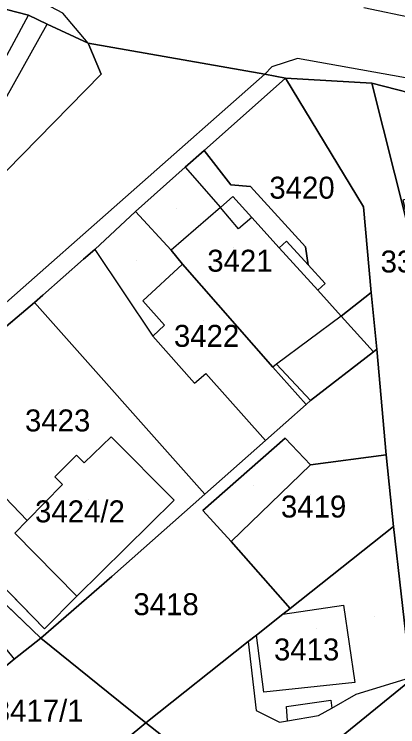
# Model space of a CAD drawing. Extents: x -262657 to -261595, y -1238015 to -1237156.
# Drawn here: x -262065.5 to -262030.6, y -1237601.5 to -1237536.7 of the extents above; entities that cross this region are included whole.
import ezdxf

# ---------------------------------------------------------------- set-up
doc = ezdxf.new("R2010")
doc.units = 0
for name, color, linetype in [('body_kn', 7, 'Continuous'), ('kladpar_druhypozemkov', 7, 'Continuous'), ('kladpar_hranice', 7, 'Continuous'), ('kladpar_parcelnecisla', 7, 'Continuous'), ('kladpar_plochy', 7, 'Continuous'), ('zappar_hrandruhpozemk', 7, 'Continuous')]:
    doc.layers.add(name, color=color, linetype=linetype)

msp = doc.modelspace()

# ---------------------------------------------------------------- linework, layer by layer
at = {"layer": 'body_kn'}
for p, q in [((-262064.22, -1237536.75), (-262064.22, -1237536.75)), ((-262062.54, -1237537.56), (-262062.54, -1237537.56)), ((-262058.8, -1237539.3), (-262058.8, -1237539.3)), ((-262058.8, -1237539.3), (-262058.8, -1237539.3)), ((-262039.74, -1237540.69), (-262039.74, -1237540.69)), ((-262042.06, -1237541.45), (-262042.06, -1237541.45)), ((-262057.6, -1237542.11), (-262057.6, -1237542.11)), ((-262042.71, -1237542.13), (-262042.71, -1237542.13)), ((-262042.71, -1237542.13), (-262042.71, -1237542.13)), ((-262040.84, -1237542.49), (-262040.84, -1237542.49)), ((-262040.84, -1237542.49), (-262040.84, -1237542.49)), ((-262032.96, -1237542.94), (-262032.96, -1237542.94)), ((-262048.24, -1237549.06), (-262048.24, -1237549.06)), ((-262049.96, -1237550.59), (-262049.96, -1237550.59)), ((-262049.96, -1237550.59), (-262049.96, -1237550.59)), ((-262045.81, -1237552.2), (-262045.81, -1237552.2)), ((-262044.02, -1237552.34), (-262044.02, -1237552.34)), ((-262045.62, -1237553.26), (-262045.62, -1237553.26)), ((-262046.75, -1237554.24), (-262046.75, -1237554.24)), ((-262046.75, -1237554.24), (-262046.75, -1237554.24)), ((-262033.72, -1237554.19), (-262033.72, -1237554.19)), ((-262054.48, -1237554.61), (-262054.48, -1237554.61)), ((-262043.9, -1237555.16), (-262043.9, -1237555.16)), ((-262043.9, -1237555.16), (-262043.9, -1237555.16)), ((-262045.1, -1237556.2), (-262045.1, -1237556.2)), ((-262040.73, -1237557.31), (-262040.73, -1237557.31)), ((-262039.01, -1237557.84), (-262039.01, -1237557.84)), ((-262058.2, -1237558.07), (-262058.2, -1237558.07)), ((-262058.2, -1237558.07), (-262058.2, -1237558.07)), ((-262051.25, -1237558.15), (-262051.25, -1237558.15)), ((-262041.4, -1237557.92), (-262041.4, -1237557.92)), ((-262041.4, -1237557.92), (-262041.4, -1237557.92)), ((-262059.22, -1237558.95), (-262059.22, -1237558.95)), ((-262050.21, -1237559.41), (-262050.21, -1237559.41)), ((-262038.76, -1237559.48), (-262038.76, -1237559.48)), ((-262038.76, -1237559.48), (-262038.76, -1237559.48)), ((-262037.22, -1237561.18), (-262037.22, -1237561.18)), ((-262062.93, -1237562.25), (-262062.93, -1237562.25)), ((-262062.93, -1237562.25), (-262062.93, -1237562.25)), ((-262037.89, -1237561.79), (-262037.89, -1237561.79)), ((-262033.04, -1237561.99), (-262033.04, -1237561.99)), ((-262063.69, -1237562.9), (-262063.69, -1237562.9)), ((-262053.81, -1237562.75), (-262053.81, -1237562.75)), ((-262035.77, -1237564.14), (-262035.77, -1237564.14)), ((-262035.77, -1237564.14), (-262035.77, -1237564.14)), ((-262051.85, -1237564.96), (-262051.85, -1237564.96)), ((-262052.92, -1237565.98), (-262052.92, -1237565.98)), ((-262032.81, -1237567.4), (-262032.81, -1237567.4)), ((-262032.5, -1237567.16), (-262032.5, -1237567.16)), ((-262032.5, -1237567.16), (-262032.5, -1237567.16)), ((-262041.98, -1237568.78), (-262041.98, -1237568.78)), ((-262041.64, -1237568.53), (-262041.64, -1237568.53)), ((-262048.08, -1237569.38), (-262048.08, -1237569.38)), ((-262049.13, -1237570.26), (-262049.13, -1237570.26)), ((-262038.54, -1237571.83), (-262038.54, -1237571.83)), ((-262038.54, -1237571.83), (-262038.54, -1237571.83)), ((-262038.95, -1237572.19), (-262038.95, -1237572.19)), ((-262056.69, -1237575.13), (-262056.69, -1237575.13)), ((-262040.87, -1237575.24), (-262040.87, -1237575.24)), ((-262042.65, -1237575.46), (-262042.65, -1237575.46)), ((-262059.85, -1237576.8), (-262059.85, -1237576.8)), ((-262031.65, -1237576.78), (-262031.65, -1237576.78)), ((-262031.65, -1237576.78), (-262031.65, -1237576.78)), ((-262059.15, -1237577.49), (-262059.15, -1237577.49)), ((-262038.55, -1237577.69), (-262038.55, -1237577.69)), ((-262061.82, -1237578.77), (-262061.82, -1237578.77)), ((-262061.13, -1237579.47), (-262061.13, -1237579.47)), ((-262048.18, -1237580.34), (-262048.18, -1237580.34)), ((-262050.98, -1237580.9), (-262050.98, -1237580.9)), ((-262048.36, -1237581.83), (-262048.36, -1237581.83)), ((-262064.35, -1237582.74), (-262064.35, -1237582.74)), ((-262064.35, -1237582.74), (-262064.35, -1237582.74)), ((-262030.98, -1237583.29), (-262030.98, -1237583.29)), ((-262030.98, -1237583.29), (-262030.98, -1237583.29)), ((-262065.49, -1237583.9), (-262065.49, -1237583.9)), ((-262045.79, -1237584.67), (-262045.79, -1237584.67)), ((-262045.79, -1237584.67), (-262045.79, -1237584.67)), ((-262056.65, -1237587.84), (-262056.65, -1237587.84)), ((-262059.83, -1237589.65), (-262059.83, -1237589.65)), ((-262040.41, -1237590.77), (-262040.41, -1237590.77)), ((-262035.55, -1237590.46), (-262035.55, -1237590.46)), ((-262041.07, -1237591.29), (-262041.07, -1237591.29)), ((-262041.07, -1237591.29), (-262041.07, -1237591.29)), ((-262062.79, -1237592.62), (-262062.79, -1237592.62)), ((-262063.12, -1237593.45), (-262063.12, -1237593.45)), ((-262063.12, -1237593.45), (-262063.12, -1237593.45)), ((-262043.47, -1237593.19), (-262043.47, -1237593.19)), ((-262044.22, -1237593.78), (-262044.22, -1237593.78)), ((-262044.22, -1237593.78), (-262044.22, -1237593.78)), ((-262065.53, -1237595.37), (-262065.53, -1237595.37)), ((-262034.52, -1237597.49), (-262034.52, -1237597.49)), ((-262056.98, -1237598.42), (-262056.98, -1237598.42)), ((-262042.8, -1237598.37), (-262042.8, -1237598.37)), ((-262034.39, -1237598.56), (-262034.39, -1237598.56)), ((-262036.69, -1237599.11), (-262036.69, -1237599.11)), ((-262040.75, -1237599.67), (-262040.75, -1237599.67)), ((-262036.62, -1237599.83), (-262036.62, -1237599.83)), ((-262043.5, -1237600.04), (-262043.5, -1237600.04)), ((-262037.81, -1237600.51), (-262037.81, -1237600.51)), ((-262053.55, -1237601.16), (-262053.55, -1237601.16)), ((-262041.38, -1237601.1), (-262041.38, -1237601.1)), ((-262040.64, -1237600.98), (-262040.64, -1237600.98))]:
    msp.add_line(p, q, dxfattribs=at)
at = {"layer": 'kladpar_druhypozemkov'}
for p, q in [((-262039.24, -1237552), (-262039.24, -1237552)), ((-262050.74, -1237554.36), (-262050.74, -1237554.36)), ((-262045.58, -1237557.94), (-262045.58, -1237557.94)), ((-262054.39, -1237559.06), (-262054.39, -1237559.06)), ((-262048.32, -1237564.51), (-262048.32, -1237564.51)), ((-262061.39, -1237572.67), (-262061.39, -1237572.67)), ((-262043.75, -1237579.56), (-262043.75, -1237579.56)), ((-262038.54, -1237580.38), (-262038.54, -1237580.38)), ((-262058.81, -1237580.82), (-262058.81, -1237580.82)), ((-262051.6, -1237589.33), (-262051.6, -1237589.33)), ((-262032.74, -1237591.47), (-262032.74, -1237591.47)), ((-262038.03, -1237592.62), (-262038.03, -1237592.62)), ((-262063.49, -1237599.25), (-262063.49, -1237599.25))]:
    msp.add_line(p, q, dxfattribs=at)
at = {"layer": 'kladpar_hranice'}
for points in [[(-262021.6, -1237545.84), (-262032.96, -1237542.94), (-262040.84, -1237542.49), (-262042.71, -1237542.13), (-262058.8, -1237539.3), (-262062.54, -1237537.56), (-262064.22, -1237536.75), (-262078.85, -1237532.95), (-262088.85, -1237530.38), (-262092.23, -1237529.48), (-262094.29, -1237528.94), (-262098.86, -1237527.8), (-262109.74, -1237525.5), (-262112.64, -1237524.8), (-262114.11, -1237524.36), (-262120.57, -1237522.58), (-262131.12, -1237519.93)], [(-262078.85, -1237532.95), (-262064.22, -1237536.75), (-262062.54, -1237537.56), (-262058.8, -1237539.3), (-262057.6, -1237542.11), (-262070.57, -1237555.33), (-262072.25, -1237554.91), (-262073.85, -1237554.47), (-262083.14, -1237552.21), (-262078.85, -1237532.95)], [(-262113.92, -1237604.85), (-262120, -1237601.39), (-262121.24, -1237601.28), (-262122.86, -1237600.4), (-262122.24, -1237599.28), (-262120.21, -1237600.52), (-262113.99, -1237594.34), (-262109.31, -1237589.66), (-262106.11, -1237586.39), (-262098.57, -1237579.94), (-262091.36, -1237573.71), (-262089.88, -1237572.05), (-262085.88, -1237567.52), (-262083.16, -1237564.51), (-262081.16, -1237562.71), (-262079.08, -1237560.37), (-262073.85, -1237554.47), (-262072.25, -1237554.91), (-262070.57, -1237555.33), (-262057.6, -1237542.11), (-262058.8, -1237539.3)], [(-262058.8, -1237539.3), (-262042.71, -1237542.13), (-262040.84, -1237542.49), (-262048.24, -1237549.06), (-262049.96, -1237550.59), (-262054.48, -1237554.61), (-262058.2, -1237558.07), (-262059.22, -1237558.95), (-262062.93, -1237562.25), (-262063.69, -1237562.9), (-262071.96, -1237569.89), (-262074.11, -1237571.73), (-262075.14, -1237572.58), (-262079.15, -1237575.94), (-262110.93, -1237604.68)], [(-262038.76, -1237559.48), (-262039.01, -1237557.84), (-262044.02, -1237552.34), (-262045.81, -1237552.2), (-262048.24, -1237549.06), (-262040.84, -1237542.49), (-262033.72, -1237554.19), (-262033.04, -1237561.99), (-262035.77, -1237564.14), (-262037.89, -1237561.79), (-262037.22, -1237561.18), (-262038.76, -1237559.48)], [(-262040.84, -1237542.49), (-262032.96, -1237542.94), (-262029.86, -1237555.24), (-262029.25, -1237560.87), (-262027.58, -1237574.94), (-262024.94, -1237587.76), (-262025.63, -1237587.92), (-262020.7, -1237605.65), (-261996.42, -1237600.03), (-261974.52, -1237594.83), (-261971.52, -1237603.32), (-261994.15, -1237607.67), (-262017.2, -1237612.1), (-262026.45, -1237613.9), (-262027.87, -1237614.17), (-262029.54, -1237597.37), (-262029.55, -1237597.08), (-262029.61, -1237595.57), (-262030.98, -1237583.29), (-262031.65, -1237576.78), (-262032.5, -1237567.16), (-262033.04, -1237561.99), (-262033.72, -1237554.19), (-262040.84, -1237542.49)], [(-262029.86, -1237555.24), (-262032.96, -1237542.94), (-262021.6, -1237545.84)], [(-262038.54, -1237571.83), (-262038.95, -1237572.19), (-262041.98, -1237568.78), (-262050.21, -1237559.41), (-262051.25, -1237558.15), (-262054.48, -1237554.61), (-262049.96, -1237550.59), (-262048.24, -1237549.06), (-262045.81, -1237552.2), (-262044.02, -1237552.34), (-262039.01, -1237557.84), (-262038.76, -1237559.48), (-262037.22, -1237561.18), (-262037.89, -1237561.79), (-262035.77, -1237564.14), (-262033.04, -1237561.99), (-262032.5, -1237567.16), (-262032.81, -1237567.4), (-262038.54, -1237571.83)], [(-262062.93, -1237562.25), (-262059.22, -1237558.95), (-262058.2, -1237558.07), (-262054.48, -1237554.61), (-262051.25, -1237558.15), (-262050.21, -1237559.41), (-262041.98, -1237568.78), (-262038.95, -1237572.19), (-262042.65, -1237575.46), (-262048.18, -1237580.34), (-262063.69, -1237562.9), (-262062.93, -1237562.25)], [(-262071.96, -1237569.89), (-262063.69, -1237562.9), (-262048.18, -1237580.34)], [(-262032.5, -1237567.16), (-262031.65, -1237576.78), (-262038.55, -1237577.69), (-262040.87, -1237575.24), (-262048.36, -1237581.83), (-262045.79, -1237584.67), (-262040.41, -1237590.77), (-262041.07, -1237591.29), (-262043.47, -1237593.19), (-262044.22, -1237593.78), (-262053.55, -1237601.16), (-262056.98, -1237598.42), (-262063.12, -1237593.45), (-262056.65, -1237587.84), (-262048.18, -1237580.34), (-262042.65, -1237575.46), (-262038.95, -1237572.19), (-262038.54, -1237571.83), (-262032.81, -1237567.4), (-262032.5, -1237567.16)], [(-262048.18, -1237580.34), (-262056.65, -1237587.84), (-262063.12, -1237593.45), (-262069.99, -1237586.88), (-262075.78, -1237579.99), (-262079.15, -1237575.94), (-262075.14, -1237572.58), (-262074.11, -1237571.73), (-262071.96, -1237569.89)], [(-262050.98, -1237580.9), (-262056.69, -1237575.13), (-262059.15, -1237577.49), (-262059.85, -1237576.8), (-262061.82, -1237578.77), (-262061.13, -1237579.47), (-262064.35, -1237582.74), (-262067.05, -1237579.95), (-262070.79, -1237576.11), (-262074.92, -1237580.13), (-262062.79, -1237592.62), (-262059.83, -1237589.65), (-262050.98, -1237580.9)], [(-262064.35, -1237582.74), (-262061.13, -1237579.47), (-262061.82, -1237578.77), (-262059.85, -1237576.8), (-262059.15, -1237577.49), (-262056.69, -1237575.13), (-262050.98, -1237580.9), (-262059.83, -1237589.65), (-262065.49, -1237583.9), (-262064.35, -1237582.74)], [(-262031.65, -1237576.78), (-262030.98, -1237583.29), (-262040.41, -1237590.77), (-262045.79, -1237584.67), (-262048.36, -1237581.83), (-262040.87, -1237575.24), (-262038.55, -1237577.69), (-262031.65, -1237576.78)], [(-262074.92, -1237580.13), (-262070.79, -1237576.11), (-262067.05, -1237579.95), (-262064.35, -1237582.74), (-262065.49, -1237583.9), (-262059.83, -1237589.65), (-262062.79, -1237592.62), (-262074.92, -1237580.13)], [(-262030.98, -1237583.29), (-262029.61, -1237595.57), (-262029.55, -1237597.08), (-262029.54, -1237597.37), (-262043.72, -1237608.92), (-262053.55, -1237601.16), (-262044.22, -1237593.78), (-262043.47, -1237593.19), (-262041.07, -1237591.29), (-262040.41, -1237590.77), (-262030.98, -1237583.29)], [(-262092.51, -1237617.76), (-262095.86, -1237615.41), (-262097.1, -1237614.58), (-262071.65, -1237593.69), (-262072.12, -1237593.14), (-262074.19, -1237590.6), (-262073.9, -1237590.31), (-262069.99, -1237586.88), (-262063.12, -1237593.45), (-262065.53, -1237595.37), (-262071.64, -1237600.45), (-262078.5, -1237606.01), (-262092.51, -1237617.76)], [(-262063.12, -1237593.45), (-262056.98, -1237598.42), (-262053.55, -1237601.16), (-262060.54, -1237606.97), (-262065.19, -1237611.06), (-262068.03, -1237613.46), (-262070.14, -1237610.88), (-262068.57, -1237609.5), (-262073.25, -1237604), (-262077.31, -1237607.46), (-262078.5, -1237606.01), (-262071.64, -1237600.45), (-262065.53, -1237595.37), (-262063.12, -1237593.45)], [(-262043.72, -1237608.92), (-262029.54, -1237597.37), (-262027.87, -1237614.17), (-262029.06, -1237615.25), (-262030.78, -1237613.12), (-262033.66, -1237615.13), (-262043.72, -1237608.92)], [(-262071.24, -1237632.02), (-262076.13, -1237628.59), (-262081.64, -1237624.86), (-262077.61, -1237621.48), (-262068.03, -1237613.46), (-262065.19, -1237611.06), (-262060.54, -1237606.97), (-262053.55, -1237601.16), (-262043.72, -1237608.92), (-262045.53, -1237610.37), (-262054.2, -1237617.65), (-262071.24, -1237632.02)]]:
    msp.add_lwpolyline(points, dxfattribs=at)
at = {"layer": 'kladpar_plochy'}
for p, q in [((-262071.96, -1237569.89), (-262063.69, -1237562.9)), ((-262063.69, -1237562.9), (-262048.18, -1237580.34)), ((-262056.69, -1237575.13), (-262059.15, -1237577.49)), ((-262050.98, -1237580.9), (-262056.69, -1237575.13)), ((-262059.85, -1237576.8), (-262061.82, -1237578.77)), ((-262059.15, -1237577.49), (-262059.85, -1237576.8)), ((-262061.82, -1237578.77), (-262061.13, -1237579.47)), ((-262061.13, -1237579.47), (-262064.35, -1237582.74)), ((-262074.92, -1237580.13), (-262062.79, -1237592.62)), ((-262064.35, -1237582.74), (-262067.05, -1237579.95)), ((-262048.18, -1237580.34), (-262056.65, -1237587.84)), ((-262059.83, -1237589.65), (-262050.98, -1237580.9)), ((-262063.12, -1237593.45), (-262069.99, -1237586.88)), ((-262056.65, -1237587.84), (-262063.12, -1237593.45)), ((-262062.79, -1237592.62), (-262059.83, -1237589.65))]:
    msp.add_line(p, q, dxfattribs=at)
for points in [[(-262021.6, -1237545.84), (-262032.96, -1237542.94), (-262040.84, -1237542.49), (-262042.71, -1237542.13), (-262058.8, -1237539.3), (-262062.54, -1237537.56), (-262064.22, -1237536.75), (-262078.85, -1237532.95), (-262088.85, -1237530.38), (-262092.23, -1237529.48), (-262094.29, -1237528.94), (-262098.86, -1237527.8), (-262109.74, -1237525.5), (-262112.64, -1237524.8), (-262114.11, -1237524.36), (-262120.57, -1237522.58), (-262131.12, -1237519.93)], [(-262070.57, -1237555.33), (-262057.6, -1237542.11), (-262058.8, -1237539.3), (-262042.71, -1237542.13), (-262040.84, -1237542.49), (-262048.24, -1237549.06), (-262049.96, -1237550.59), (-262054.48, -1237554.61), (-262058.2, -1237558.07), (-262059.22, -1237558.95), (-262062.93, -1237562.25), (-262063.69, -1237562.9), (-262071.96, -1237569.89)]]:
    msp.add_lwpolyline(points, dxfattribs=at)
for points in [[(-262078.85, -1237532.95), (-262064.22, -1237536.75), (-262062.54, -1237537.56), (-262058.8, -1237539.3), (-262057.6, -1237542.11), (-262070.57, -1237555.33), (-262072.25, -1237554.91), (-262073.85, -1237554.47), (-262083.14, -1237552.21)], [(-262038.76, -1237559.48), (-262039.01, -1237557.84), (-262044.02, -1237552.34), (-262045.81, -1237552.2), (-262048.24, -1237549.06), (-262040.84, -1237542.49), (-262033.72, -1237554.19), (-262033.04, -1237561.99), (-262035.77, -1237564.14), (-262037.89, -1237561.79), (-262037.22, -1237561.18)], [(-262040.84, -1237542.49), (-262032.96, -1237542.94), (-262029.86, -1237555.24), (-262029.25, -1237560.87), (-262027.58, -1237574.94), (-262024.94, -1237587.76), (-262025.63, -1237587.92), (-262020.7, -1237605.65), (-261996.42, -1237600.03), (-261974.52, -1237594.83), (-261971.52, -1237603.32), (-261994.15, -1237607.67), (-262017.2, -1237612.1), (-262026.45, -1237613.9), (-262027.87, -1237614.17), (-262029.54, -1237597.37), (-262029.55, -1237597.08), (-262029.61, -1237595.57), (-262030.98, -1237583.29), (-262031.65, -1237576.78), (-262032.5, -1237567.16), (-262033.04, -1237561.99), (-262033.72, -1237554.19)], [(-262009.62, -1237556.09), (-262009.52, -1237556.43), (-262013.23, -1237557.53), (-262021.57, -1237561.48), (-262028.2, -1237564.31), (-262028.83, -1237560.77), (-262027.22, -1237560.39), (-262026.97, -1237561.32), (-262016.83, -1237558.58), (-262017, -1237557.97), (-262010.43, -1237556.41), (-262010.95, -1237553.56), (-262018.33, -1237552.98), (-262019.4, -1237548.91), (-262029.55, -1237551.65), (-262029.11, -1237553.29), (-262030.15, -1237553.58), (-262029.72, -1237555.23), (-262029.86, -1237555.24), (-262032.96, -1237542.94), (-262021.6, -1237545.84), (-262002.32, -1237549.14), (-262005.42, -1237555.01), (-262005.41, -1237555.13)], [(-262038.54, -1237571.83), (-262038.95, -1237572.19), (-262041.98, -1237568.78), (-262050.21, -1237559.41), (-262051.25, -1237558.15), (-262054.48, -1237554.61), (-262049.96, -1237550.59), (-262048.24, -1237549.06), (-262045.81, -1237552.2), (-262044.02, -1237552.34), (-262039.01, -1237557.84), (-262038.76, -1237559.48), (-262037.22, -1237561.18), (-262037.89, -1237561.79), (-262035.77, -1237564.14), (-262033.04, -1237561.99), (-262032.5, -1237567.16), (-262032.81, -1237567.4)], [(-262062.93, -1237562.25), (-262059.22, -1237558.95), (-262058.2, -1237558.07), (-262054.48, -1237554.61), (-262051.25, -1237558.15), (-262050.21, -1237559.41), (-262041.98, -1237568.78), (-262038.95, -1237572.19), (-262042.65, -1237575.46), (-262048.18, -1237580.34), (-262063.69, -1237562.9)], [(-262032.5, -1237567.16), (-262031.65, -1237576.78), (-262038.55, -1237577.69), (-262040.87, -1237575.24), (-262048.36, -1237581.83), (-262045.79, -1237584.67), (-262040.41, -1237590.77), (-262041.07, -1237591.29), (-262043.47, -1237593.19), (-262044.22, -1237593.78), (-262053.55, -1237601.16), (-262056.98, -1237598.42), (-262063.12, -1237593.45), (-262056.65, -1237587.84), (-262048.18, -1237580.34), (-262042.65, -1237575.46), (-262038.95, -1237572.19), (-262038.54, -1237571.83), (-262032.81, -1237567.4)], [(-262064.35, -1237582.74), (-262061.13, -1237579.47), (-262061.82, -1237578.77), (-262059.85, -1237576.8), (-262059.15, -1237577.49), (-262056.69, -1237575.13), (-262050.98, -1237580.9), (-262059.83, -1237589.65), (-262065.49, -1237583.9)], [(-262031.65, -1237576.78), (-262030.98, -1237583.29), (-262040.41, -1237590.77), (-262045.79, -1237584.67), (-262048.36, -1237581.83), (-262040.87, -1237575.24), (-262038.55, -1237577.69)], [(-262074.92, -1237580.13), (-262070.79, -1237576.11), (-262067.05, -1237579.95), (-262064.35, -1237582.74), (-262065.49, -1237583.9), (-262059.83, -1237589.65), (-262062.79, -1237592.62)], [(-262030.98, -1237583.29), (-262029.61, -1237595.57), (-262029.55, -1237597.08), (-262029.54, -1237597.37), (-262043.72, -1237608.92), (-262053.55, -1237601.16), (-262044.22, -1237593.78), (-262043.47, -1237593.19), (-262041.07, -1237591.29), (-262040.41, -1237590.77)], [(-262092.51, -1237617.76), (-262095.86, -1237615.41), (-262097.1, -1237614.58), (-262071.65, -1237593.69), (-262072.12, -1237593.14), (-262074.19, -1237590.6), (-262073.9, -1237590.31), (-262069.99, -1237586.88), (-262063.12, -1237593.45), (-262065.53, -1237595.37), (-262071.64, -1237600.45), (-262078.5, -1237606.01)], [(-262063.12, -1237593.45), (-262056.98, -1237598.42), (-262053.55, -1237601.16), (-262060.54, -1237606.97), (-262065.19, -1237611.06), (-262068.03, -1237613.46), (-262070.14, -1237610.88), (-262068.57, -1237609.5), (-262073.25, -1237604), (-262077.31, -1237607.46), (-262078.5, -1237606.01), (-262071.64, -1237600.45), (-262065.53, -1237595.37)], [(-262043.72, -1237608.92), (-262029.54, -1237597.37), (-262027.87, -1237614.17), (-262029.06, -1237615.25), (-262030.78, -1237613.12), (-262033.66, -1237615.13)], [(-262071.24, -1237632.02), (-262076.13, -1237628.59), (-262081.64, -1237624.86), (-262077.61, -1237621.48), (-262068.03, -1237613.46), (-262065.19, -1237611.06), (-262060.54, -1237606.97), (-262053.55, -1237601.16), (-262043.72, -1237608.92), (-262045.53, -1237610.37), (-262054.2, -1237617.65)]]:
    msp.add_lwpolyline(points, close=True, dxfattribs=at)
at = {"layer": 'zappar_hrandruhpozemk'}
for p, q in [((-262033.7, -1237536.05), (-262003.5, -1237542.37)), ((-262073.85, -1237554.47), (-262064.22, -1237536.75)), ((-262072.25, -1237554.91), (-262062.54, -1237537.56)), ((-261992.8, -1237549.03), (-262039.74, -1237540.69)), ((-262042.71, -1237542.13), (-262113.92, -1237604.85)), ((-262046.75, -1237554.24), (-262051.25, -1237558.15)), ((-262045.1, -1237556.2), (-262046.75, -1237554.24)), ((-262043.9, -1237555.16), (-262041.4, -1237557.92)), ((-262058.2, -1237558.07), (-262052.92, -1237565.98)), ((-262041.4, -1237557.92), (-262037.89, -1237561.79)), ((-262035.77, -1237564.14), (-262041.64, -1237568.53)), ((-262035.77, -1237564.14), (-262032.81, -1237567.4)), ((-262052.92, -1237565.98), (-262049.13, -1237570.26)), ((-262041.64, -1237568.53), (-262041.98, -1237568.78)), ((-262041.64, -1237568.53), (-262038.54, -1237571.83)), ((-262045.79, -1237584.67), (-262038.55, -1237577.69)), ((-262069.19, -1237590.89), (-262065.53, -1237595.37)), ((-262041.07, -1237591.29), (-262035.55, -1237590.46)), ((-262035.55, -1237590.46), (-262034.52, -1237597.49)), ((-262040.75, -1237599.67), (-262036.69, -1237599.11)), ((-262036.69, -1237599.11), (-262036.62, -1237599.83)), ((-262040.64, -1237600.98), (-262040.75, -1237599.67)), ((-262040.64, -1237600.98), (-262037.81, -1237600.51))]:
    msp.add_line(p, q, dxfattribs=at)
for points in [[(-262058.8, -1237539.3), (-262061.1, -1237536.57), (-262064.52, -1237534.73)], [(-262039.74, -1237540.69), (-262042.06, -1237541.45), (-262042.71, -1237542.13)], [(-262049.96, -1237550.59), (-262046.75, -1237554.24), (-262045.62, -1237553.26), (-262043.9, -1237555.16), (-262045.1, -1237556.2)], [(-262038.76, -1237559.48), (-262040.73, -1237557.31), (-262041.4, -1237557.92)], [(-262052.92, -1237565.98), (-262051.85, -1237564.96), (-262053.81, -1237562.75), (-262050.21, -1237559.41)], [(-262049.13, -1237570.26), (-262048.08, -1237569.38), (-262042.65, -1237575.46)], [(-262034.52, -1237597.49), (-262042.8, -1237598.37), (-262043.47, -1237593.19)], [(-262044.22, -1237593.78), (-262043.5, -1237600.04), (-262041.38, -1237601.1), (-262040.64, -1237600.98)], [(-262037.81, -1237600.51), (-262036.62, -1237599.83), (-262034.39, -1237598.56), (-262029.55, -1237597.08)]]:
    msp.add_lwpolyline(points, dxfattribs=at)

# ---------------------------------------------------------------- texts
at = {"layer": 'kladpar_parcelnecisla'}
for s, p in [('3420', (-262042.3, -1237553.45)), ('3421', (-262047.95, -1237560.1)), ('3395/2', (-262032.167, -1237560.17)), ('3422', (-262050.986, -1237566.94)), ('3423', (-262064.551, -1237574.64)), ('3419', (-262041.243, -1237582.48)), ('3424/2', (-262063.636, -1237582.92)), ('3418', (-262054.677, -1237591.37)), ('3413', (-262041.875, -1237595.49)), ('3417/1', (-262067.396, -1237601.07))]:
    msp.add_text(s, height=2, dxfattribs=at).set_placement(p)

doc.saveas('drawing.dxf')
